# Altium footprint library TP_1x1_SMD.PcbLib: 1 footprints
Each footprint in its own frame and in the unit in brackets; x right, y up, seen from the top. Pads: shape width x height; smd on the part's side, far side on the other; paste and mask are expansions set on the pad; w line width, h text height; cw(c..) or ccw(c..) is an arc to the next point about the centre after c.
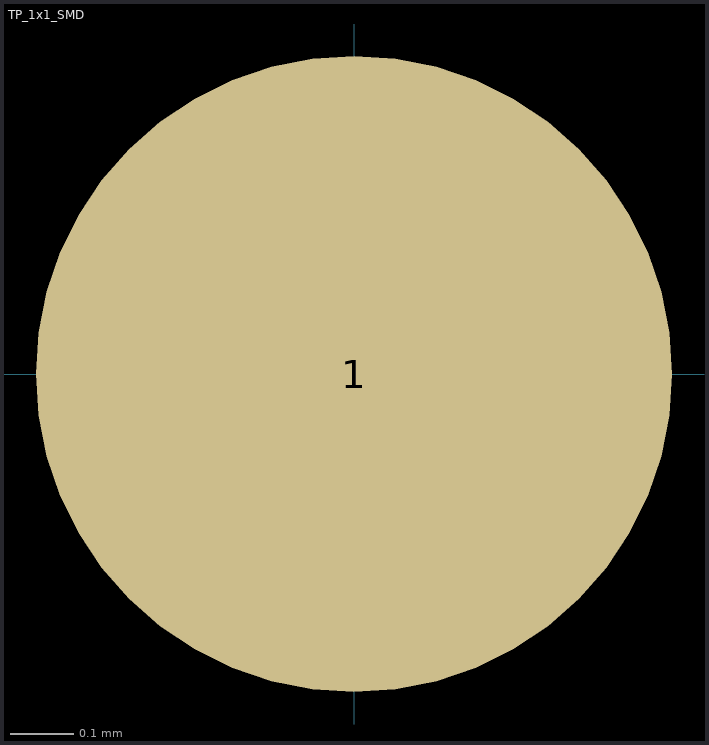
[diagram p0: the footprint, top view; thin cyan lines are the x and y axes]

## TP_1x1_SMD [mm] "1.00mm SMD Pad"
pads (1):
  round 1 smd paste-1 mask+0.05: 1(0,0)
M15 Guard TOP:
  lines w0.1: -0.3,0 0.3,0 ; 0,-0.3 0,0.3
3D body: height 0.25, standoff 0, extent 0.65,0 0.65,0
3D body: height 0.04, standoff 0, extent -0.498,-0.499 0.498,0.499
